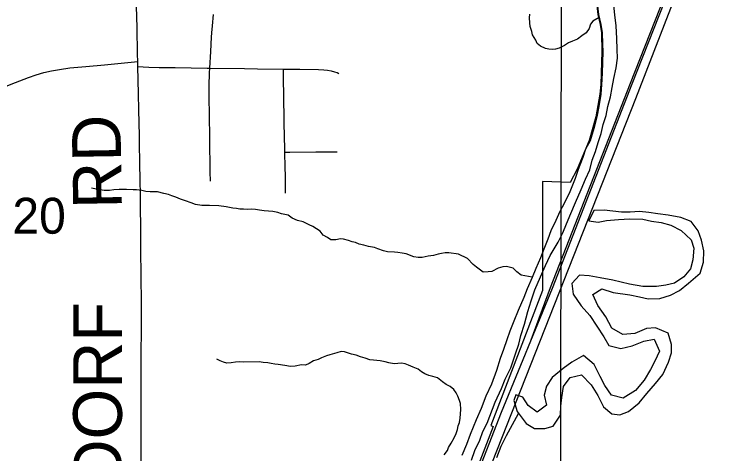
# Model space of a CAD drawing. Extents: x 0 to 34, y 0 to 22.
# Drawn here: x 7.284 to 8.111, y 17.466 to 17.979 of the extents above; entities that cross this region are included whole.
import ezdxf

# ---------------------------------------------------------------- set-up
doc = ezdxf.new("R2010")
doc.units = 0
for name, color, linetype in [('GM_X_Major_River', 7, 'Continuous'), ('GM_X_Minor_River', 7, 'Continuous'), ('GM_X_Rail_Line', 7, 'Continuous'), ('GM_X_Section', 7, 'Continuous'), ('GM_X_Section_Text', 7, 'Continuous'), ('GM_X_State_Route', 7, 'Continuous'), ('GM_X_Township_Road', 7, 'Continuous'), ('GM_X_Township_Road_Text', 7, 'Continuous'), ('GM_X_Unincorporated', 7, 'Continuous')]:
    doc.layers.add(name, color=color, linetype=linetype)

msp = doc.modelspace()

# ---------------------------------------------------------------- linework, layer by layer
at = {"layer": 'GM_X_Major_River'}
for points in [[(7.8167, 17.45925), (7.82079, 17.47028), (7.82676, 17.48246), (7.8301, 17.49234), (7.83496, 17.50224), (7.84464, 17.52658), (7.85172, 17.54257), (7.85619, 17.5536), (7.86254, 17.56692), (7.86811, 17.58327), (7.8722, 17.5943), (7.8744, 17.60455), (7.87847, 17.61786), (7.88254, 17.6323), (7.88662, 17.64485), (7.89069, 17.65777), (7.89741, 17.67299), (7.903, 17.68593), (7.9086, 17.69773), (7.91796, 17.71335), (7.92319, 17.724), (7.92766, 17.73466), (7.9325, 17.74683), (7.93809, 17.75939), (7.9448, 17.77461), (7.94964, 17.78678), (7.95487, 17.79782), (7.95744, 17.80883), (7.96154, 17.8191), (7.9645, 17.82937), (7.96783, 17.84001), (7.97041, 17.85065), (7.97375, 17.86091), (7.97595, 17.87155), (7.9789, 17.88295), (7.98072, 17.89358), (7.98292, 17.90421), (7.98548, 17.91675), (7.98692, 17.92776), (7.98685, 17.938), (7.98638, 17.95089), (7.98553, 17.96567), (7.98392, 17.97856), (7.98271, 17.98954)], [(7.96378, 17.98902), (7.96498, 17.97879), (7.96771, 17.96706), (7.9693, 17.95721), (7.96976, 17.9447), (7.96983, 17.93522), (7.96953, 17.92308), (7.96924, 17.91018), (7.96858, 17.8969), (7.96752, 17.8859), (7.96534, 17.87147), (7.96278, 17.85932), (7.95983, 17.84716), (7.95501, 17.83157), (7.94978, 17.82167), (7.94682, 17.81217), (7.94123, 17.79809)], [(7.94123, 17.79809), (7.93752, 17.78745), (7.93157, 17.77185), (7.92522, 17.75929), (7.91998, 17.74901), (7.91513, 17.73873), (7.90953, 17.72656), (7.90582, 17.71667), (7.90135, 17.70526), (7.89725, 17.69499), (7.89204, 17.68243), (7.88757, 17.67216), (7.8816, 17.65884), (7.87788, 17.64895), (7.87117, 17.63373), (7.86633, 17.62118), (7.86149, 17.60939), (7.85815, 17.5995), (7.85406, 17.58809), (7.85034, 17.57783), (7.8459, 17.56376), (7.84032, 17.54779), (7.8336, 17.53371), (7.82803, 17.51925), (7.82244, 17.50594), (7.81535, 17.4892), (7.81089, 17.47741), (7.80568, 17.46447)]]:
    msp.add_lwpolyline(points, dxfattribs=at)
at = {"layer": 'GM_X_Minor_River'}
for points in [[(7.96577, 17.97541), (7.95813, 17.97118), (7.95552, 17.96735), (7.95407, 17.96239), (7.95071, 17.95741), (7.94543, 17.95392), (7.94053, 17.95006), (7.93448, 17.9477), (7.92994, 17.94574), (7.92542, 17.94264), (7.91899, 17.93951), (7.91482, 17.93832), (7.91103, 17.93789), (7.90684, 17.93821), (7.90302, 17.9393), (7.89728, 17.94188), (7.89344, 17.94487), (7.89186, 17.94903), (7.88798, 17.95505), (7.88717, 17.95884), (7.88519, 17.96489), (7.88476, 17.96907), (7.88468, 17.97476), (7.88501, 17.97932)], [(7.88767, 17.6724), (7.87489, 17.67492), (7.86989, 17.67866), (7.86527, 17.68315), (7.85764, 17.68495), (7.85346, 17.68451), (7.84816, 17.68293), (7.8406, 17.67903), (7.83643, 17.67859), (7.83034, 17.67851), (7.82266, 17.68411), (7.81882, 17.68709), (7.81226, 17.69422), (7.80155, 17.6994), (7.7905, 17.70077), (7.78632, 17.70071), (7.78176, 17.70027), (7.77797, 17.69946), (7.77266, 17.69787), (7.76621, 17.69703), (7.75938, 17.69542), (7.75482, 17.69536), (7.74987, 17.69605), (7.74069, 17.69972), (7.73612, 17.70042), (7.73117, 17.70112), (7.72697, 17.70182), (7.71898, 17.70209), (7.71441, 17.70317), (7.70753, 17.70536), (7.7037, 17.70721), (7.69684, 17.70826), (7.6915, 17.70971), (7.68578, 17.71115), (7.68157, 17.71299), (7.67776, 17.7137), (7.67356, 17.71516), (7.66783, 17.71661), (7.66402, 17.71732), (7.65871, 17.71611), (7.65301, 17.71603), (7.64917, 17.71864), (7.64419, 17.72161), (7.64032, 17.72611), (7.63611, 17.72872), (7.63189, 17.7317), (7.62768, 17.73354), (7.62079, 17.73687), (7.61392, 17.73868), (7.6078, 17.74126), (7.60319, 17.74461), (7.59556, 17.74641), (7.59098, 17.74787), (7.58526, 17.74893), (7.58031, 17.74963), (7.57536, 17.74994), (7.56965, 17.75062), (7.56507, 17.75132), (7.56013, 17.75164), (7.55594, 17.75158), (7.55099, 17.75189), (7.54681, 17.75184), (7.543, 17.75255), (7.53881, 17.75287), (7.5308, 17.75466), (7.52242, 17.75569), (7.51139, 17.75593), (7.50721, 17.75587), (7.50264, 17.75619), (7.4954, 17.75723), (7.49005, 17.75906), (7.48355, 17.76163), (7.47782, 17.76345), (7.47247, 17.76566), (7.4675, 17.7675), (7.46368, 17.76896), (7.45834, 17.77003), (7.45109, 17.77183), (7.44652, 17.77215), (7.44234, 17.7721), (7.43739, 17.77241), (7.43282, 17.77349), (7.42634, 17.77416), (7.42253, 17.77449), (7.41492, 17.77477), (7.40618, 17.77465), (7.4001, 17.77419), (7.39516, 17.77337), (7.38869, 17.77366), (7.38184, 17.77471), (7.37802, 17.77542), (7.37383, 17.77612)], [(7.87009, 17.51578), (7.88079, 17.50183), (7.89029, 17.49621), (7.90242, 17.49592), (7.91224, 17.49865), (7.92049, 17.51161), (7.92117, 17.52223), (7.92224, 17.5321), (7.92404, 17.54501), (7.93192, 17.55531), (7.94516, 17.55844), (7.95622, 17.54677), (7.96426, 17.53431), (7.97079, 17.52147), (7.98032, 17.5132), (7.98979, 17.51213), (7.99999, 17.516), (8.01242, 17.52595), (8.02105, 17.53702), (8.0312, 17.54847), (8.03984, 17.55915), (8.04656, 17.57324), (8.04989, 17.58426), (8.04982, 17.59412), (8.04594, 17.60736), (8.03151, 17.61332), (8.02091, 17.61248), (8.00732, 17.60669), (7.99331, 17.60545), (7.98038, 17.61294), (7.97348, 17.62616), (7.96429, 17.63936), (7.95815, 17.65221), (7.96871, 17.65874), (7.98199, 17.65467), (8.00132, 17.65178), (8.0127, 17.64959), (8.02294, 17.64739), (8.03658, 17.64749), (8.04867, 17.65138), (8.05924, 17.65676), (8.06978, 17.66557), (8.08333, 17.67705), (8.08741, 17.68997), (8.0877, 17.70325), (8.08496, 17.71574), (8.0811, 17.72633), (8.07307, 17.73727), (8.06092, 17.74211), (8.04613, 17.74465), (8.034, 17.74646), (8.02376, 17.74789), (8.01277, 17.74895), (8.0018, 17.74811), (7.99157, 17.74841), (7.98171, 17.74947), (7.97148, 17.75054), (7.95936, 17.75007), (7.95376, 17.73827), (7.96438, 17.73645), (7.97421, 17.73842), (7.98822, 17.73966), (8.00147, 17.74052), (8.01662, 17.74026), (8.02686, 17.73768), (8.03786, 17.73624), (8.04924, 17.7333), (8.0614, 17.72694), (8.07284, 17.71603), (8.07594, 17.70619), (8.0749, 17.69253), (8.07194, 17.68227), (8.06443, 17.67273), (8.05349, 17.66544), (8.04328, 17.66309), (8.03269, 17.6615), (8.0164, 17.66175), (8.00086, 17.66429), (7.99138, 17.66649), (7.98151, 17.66907), (7.96672, 17.67162), (7.95421, 17.67418), (7.94284, 17.67485), (7.93382, 17.66492), (7.93542, 17.6528), (7.9446, 17.63921), (7.95491, 17.62792), (7.97098, 17.60301), (7.97711, 17.59281), (7.99077, 17.58912), (8.00401, 17.59226), (8.0176, 17.59767), (8.02971, 17.60004), (8.03586, 17.58605), (8.03064, 17.57463), (8.02541, 17.56473), (8.01829, 17.55254), (8.00815, 17.54033), (7.99382, 17.5315), (7.98017, 17.53481), (7.97213, 17.54613)], [(7.78519, 17.46518), (7.78893, 17.47018), (7.79002, 17.47399), (7.793, 17.47896), (7.79672, 17.48509), (7.79894, 17.49006), (7.8004, 17.49502), (7.80149, 17.49921), (7.80296, 17.50303), (7.80365, 17.50798), (7.80396, 17.5133), (7.80428, 17.51824), (7.80419, 17.52508), (7.803, 17.52886), (7.80104, 17.53377), (7.79909, 17.53754), (7.79638, 17.54131), (7.79214, 17.54505), (7.78717, 17.54726), (7.78294, 17.55062), (7.77718, 17.55511), (7.77184, 17.55655), (7.76725, 17.55801), (7.76267, 17.55985), (7.75845, 17.56207), (7.75461, 17.56506), (7.74887, 17.56764), (7.74352, 17.56985), (7.7397, 17.57132), (7.73512, 17.57202), (7.72676, 17.57153), (7.72067, 17.57258), (7.71609, 17.57366), (7.71037, 17.57473), (7.70275, 17.57577), (7.69856, 17.57609), (7.69283, 17.57791), (7.68748, 17.57974), (7.68252, 17.58157), (7.67718, 17.58264), (7.67336, 17.58373), (7.66877, 17.58557), (7.66496, 17.5859), (7.66004, 17.58431), (7.65171, 17.58192), (7.64792, 17.58073), (7.64224, 17.57838), (7.63809, 17.57642), (7.63278, 17.57483), (7.6275, 17.57172), (7.62334, 17.56977), (7.61877, 17.57009), (7.61156, 17.56885), (7.60586, 17.56839), (7.59938, 17.56945), (7.59138, 17.57048), (7.58757, 17.57119), (7.58338, 17.57189), (7.57957, 17.5726), (7.57424, 17.57291), (7.56928, 17.57361), (7.55065, 17.57336), (7.54684, 17.57368), (7.54191, 17.57324), (7.53659, 17.57241), (7.53165, 17.57234), (7.52783, 17.57343), (7.52401, 17.5749), (7.52018, 17.57675)], [(7.97213, 17.54613), (7.96676, 17.55671), (7.95985, 17.57069), (7.94728, 17.58121), (7.93369, 17.57352), (7.9239, 17.56587), (7.91109, 17.55553), (7.90435, 17.54524), (7.90177, 17.53498), (7.90412, 17.52324), (7.89357, 17.5152), (7.88292, 17.5227), (7.87679, 17.53252)], [(7.87679, 17.53252), (7.86868, 17.53528), (7.86609, 17.52881), (7.87009, 17.51578)], [(7.8466, 17.46213), (7.85143, 17.47544), (7.85778, 17.488), (7.87174, 17.51363)]]:
    msp.add_lwpolyline(points, dxfattribs=at)
at = {"layer": 'GM_X_Rail_Line'}
for points in [[(7.88643, 17.59932), (7.90898, 17.6604), (8.00201, 17.89866), (8.29237, 18.63494), (8.4135, 18.9454), (8.4555, 19.05327), (8.53436, 19.25473), (8.58949, 19.39524), (8.61432, 19.45991), (8.63417, 19.51046), (8.64593, 19.53884), (8.65857, 19.56429), (8.67308, 19.59193), (8.68775, 19.61833), (8.69982, 19.64023), (8.73811, 19.70956), (8.7826, 19.78941), (8.82382, 19.86339), (8.85051, 19.9123), (8.86685, 19.94635), (8.88097, 19.97923), (8.9, 20.02438)], [(7.75733, 17.27239), (7.85176, 17.51498), (7.91117, 17.65953), (8.0042, 17.8978), (8.29457, 18.63409), (8.4157, 18.94455), (8.45769, 19.05242), (8.53655, 19.25388), (8.59169, 19.39439), (8.61652, 19.45906), (8.63635, 19.50959), (8.64808, 19.53787), (8.66067, 19.56322), (8.67516, 19.59082), (8.68982, 19.6172), (8.70189, 19.6391), (8.74017, 19.70843), (8.78466, 19.78827), (8.82588, 19.86226), (8.85261, 19.91123), (8.86899, 19.94538), (8.88314, 19.97832), (8.9, 20.01832)], [(6.46064, 14.09996), (6.45713, 14.19536), (6.44773, 14.44053), (6.45238, 14.50813), (6.46367, 14.55678), (6.48566, 14.6083), (6.54727, 14.69788), (6.88614, 15.13086), (7.24057, 15.57245), (7.33381, 15.68245), (7.38513, 15.75625), (7.42249, 15.82237), (7.44954, 15.91319), (7.4686, 16.00837), (7.58162, 16.56482), (7.64362, 16.88689), (7.66845, 17.00953), (7.69755, 17.09135), (7.75798, 17.24541), (8.00835, 17.8807), (8.14941, 18.24545), (8.27735, 18.55925), (8.29339, 18.61839), (8.45401, 19.28155)]]:
    msp.add_lwpolyline(points, dxfattribs=at)
at = {"layer": 'GM_X_Section'}
msp.add_lwpolyline([(7.92171, 18.27008), (7.92008, 17.25434), (6.92373, 17.24282), (6.91054, 18.26226)], close=True, dxfattribs=at)
at = {"layer": 'GM_X_State_Route'}
msp.add_lwpolyline([(7.94491, 18.55635), (7.91397, 18.26868), (8.09676, 18.26998), (7.99986, 18.01859), (7.96118, 18.01792), (7.96193, 18.00018), (7.96397, 17.97896), (7.9667, 17.96722), (7.96828, 17.95737), (7.96882, 17.93538), (7.96852, 17.92325), (7.96757, 17.89707), (7.9665, 17.88606), (7.96176, 17.85948), (7.954, 17.83174), (7.94581, 17.81233), (7.94022, 17.79826), (7.93199, 17.78282), (7.89972, 17.78393), (7.89971, 17.657), (7.83925, 17.4996), (7.84206, 17.49846), (7.76632, 17.30128)], dxfattribs=at)
at = {"layer": 'GM_X_Township_Road'}
msp.add_line((7.4281, 17.91825), (7.42798, 17.9238), dxfattribs=at)
for points in [[(7.42798, 17.9238), (7.4278, 17.93242), (7.42705, 17.96349), (7.42636, 17.9883), (7.42564, 18.01933), (7.42521, 18.04056), (7.42514, 18.04438)], [(7.5118, 17.91634), (7.513, 17.93557), (7.51385, 17.95222), (7.51426, 17.95748), (7.5149, 17.96569), (7.51613, 17.97883)], [(7.25004, 17.88487), (7.25447, 17.88673), (7.25584, 17.8873), (7.28037, 17.89747), (7.30064, 17.90543), (7.30947, 17.90839), (7.3184, 17.91097), (7.32745, 17.91308), (7.33661, 17.91471), (7.34891, 17.9164), (7.36749, 17.91826), (7.38921, 17.92019), (7.42023, 17.92308), (7.42798, 17.9238)], [(7.43133, 17.73659), (7.43126, 17.7478), (7.4312, 17.754), (7.43104, 17.76939), (7.43078, 17.78467), (7.43035, 17.80611), (7.43009, 17.82784), (7.42988, 17.83713), (7.42904, 17.86758), (7.42876, 17.88608), (7.4281, 17.91825)], [(7.4281, 17.91825), (7.43427, 17.9178), (7.44077, 17.91732), (7.45306, 17.91697), (7.47162, 17.91696), (7.50879, 17.91639), (7.5118, 17.91634)], [(7.51254, 17.78449), (7.51241, 17.79518), (7.51231, 17.80241), (7.51221, 17.8103), (7.51209, 17.81902), (7.512, 17.82626), (7.51181, 17.8403), (7.51159, 17.8558), (7.51136, 17.86722), (7.51109, 17.87654), (7.51109, 17.88266), (7.51109, 17.88941), (7.51109, 17.8956), (7.51147, 17.9108), (7.5118, 17.91634)], [(7.5118, 17.91634), (7.55213, 17.91563), (7.56759, 17.91541), (7.59768, 17.91516)], [(7.59927, 17.81834), (7.59917, 17.82626), (7.59901, 17.83241), (7.598, 17.88165), (7.59766, 17.90627), (7.59766, 17.90987), (7.59768, 17.91516)], [(7.59768, 17.91516), (7.61699, 17.915), (7.6387, 17.91469), (7.64491, 17.91429), (7.64898, 17.91394), (7.65332, 17.91315), (7.6574, 17.9121), (7.66015, 17.91104), (7.66214, 17.90987)], [(7.59927, 17.81834), (7.60529, 17.81839), (7.6356, 17.81865), (7.64773, 17.81873), (7.65537, 17.81867), (7.6603, 17.81863)], [(7.60011, 17.77062), (7.60016, 17.77424), (7.60014, 17.78098), (7.60012, 17.78933), (7.59971, 17.80164), (7.59929, 17.81702), (7.59927, 17.81834)], [(7.4319, 17.45541), (7.43196, 17.47096), (7.43188, 17.48648), (7.43176, 17.52688), (7.43191, 17.56416), (7.43206, 17.5766), (7.43205, 17.5793), (7.43205, 17.58473), (7.43215, 17.6094), (7.43219, 17.62074), (7.43222, 17.62765), (7.43224, 17.63466), (7.43233, 17.64085), (7.43173, 17.67505), (7.43153, 17.70302), (7.43157, 17.70926), (7.43148, 17.71111), (7.43133, 17.73659)]]:
    msp.add_lwpolyline(points, dxfattribs=at)
at = {"layer": 'GM_X_Unincorporated'}
msp.add_lwpolyline([(8.9, 17.26302), (8.9, 18.27692), (7.92171, 18.27008), (7.92008, 17.25434)], close=True, dxfattribs=at)

# ---------------------------------------------------------------- texts
at = {"layer": 'GM_X_Section_Text'}
msp.add_text('20', height=0.041856, rotation=0.00001, dxfattribs=at).set_placement((7.28182, 17.72319))
at = {"layer": 'GM_X_Township_Road_Text'}
for s, rotation, p in [('RD', 90.95273, (7.40948, 17.75263)), ('BATDORF', 90, (7.40946, 17.28062))]:
    msp.add_text(s, height=0.056818, rotation=rotation, dxfattribs=at).set_placement(p)

doc.saveas('drawing.dxf')
